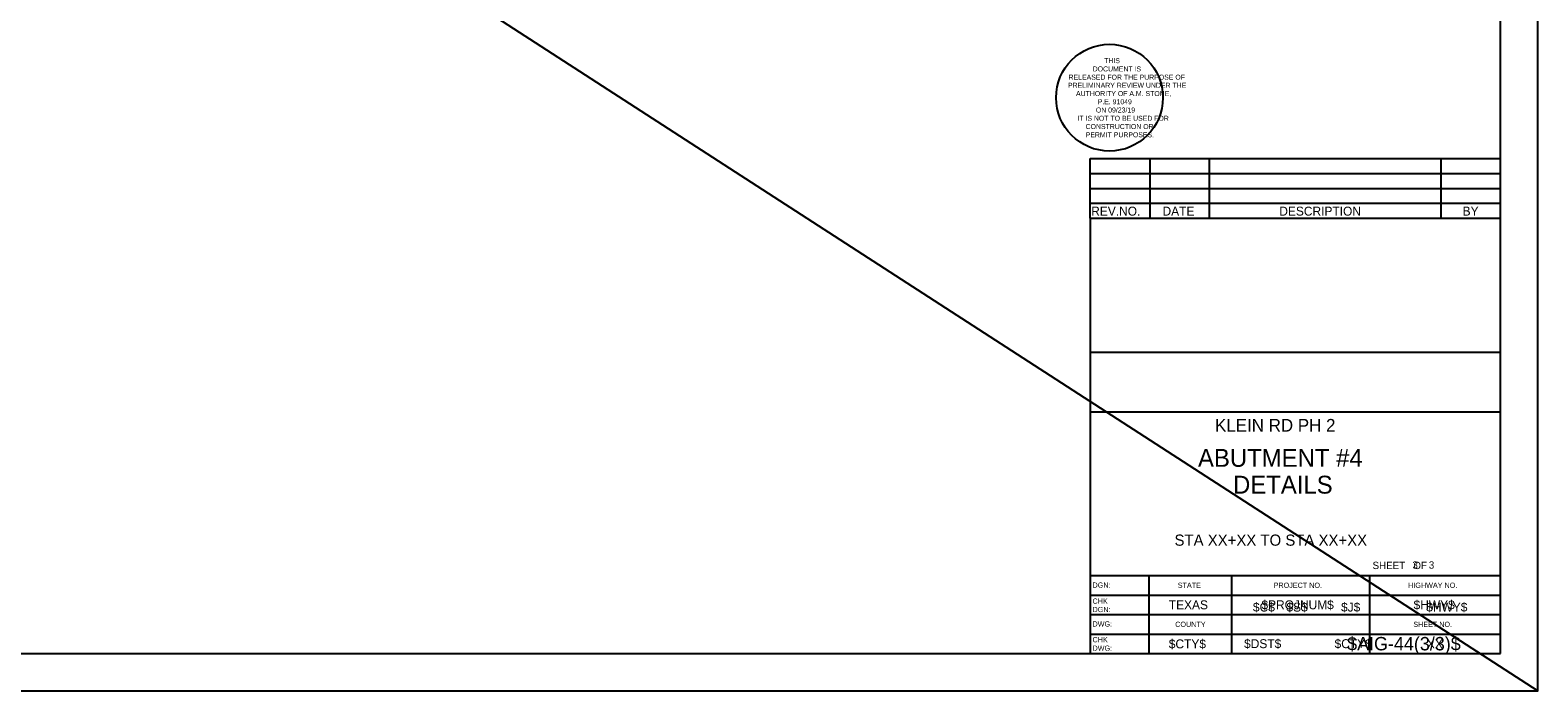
# Model space of a CAD drawing. Extents: x 926 to 1074, y 990 to 1081.
# Drawn here: x 1013.75 to 1034, y 1023 to 1031.88 of the extents above; entities that cross this region are included whole.
import ezdxf

# ---------------------------------------------------------------- set-up
doc = ezdxf.new("R2010")
doc.units = 0
for name, color, linetype in [('BORD_lines_major', 7, 'Continuous'), ('BORD_lines_minor', 7, 'Continuous'), ('BORD_text_large_1', 7, 'Continuous'), ('BORD_text_large_2', 7, 'Continuous'), ('BORD_text_SHEET', 7, 'Continuous'), ('BORD_text_small_1', 7, 'Continuous'), ('BORD_text_small_3', 7, 'Continuous'), ('BORD_text_small_proj', 7, 'Continuous'), ('C-MS-ANNO-TTLB-STMP', 7, 'Continuous'), ('D_BATCH_PLOT', 7, 'Continuous'), ('D_SHEET', 7, 'Continuous'), ('D_SHEET_NUM_CODE', 7, 'Continuous'), ('D_SHEET_TXT_SUB_CODE', 7, 'Continuous'), ('Working Level 1', 7, 'Continuous')]:
    doc.layers.add(name, color=color, linetype=linetype)

msp = doc.modelspace()

# ---------------------------------------------------------------- linework, layer by layer
at = {"layer": 'BORD_lines_major'}
for p, q in [((1033.5, 1023.5), (1033.5, 1044.382)), ((1002.413, 1023.5), (1033.5, 1023.5))]:
    msp.add_line(p, q, dxfattribs=at)
at = {"layer": 'BORD_lines_minor'}
for p, q in [((1027.988, 1030.15), (1033.5, 1030.15)), ((1027.988, 1029.35), (1027.988, 1030.15)), ((1028.788, 1030.15), (1028.788, 1029.35)), ((1029.588, 1030.15), (1029.588, 1029.35)), ((1032.7, 1029.35), (1032.7, 1030.15)), ((1027.988, 1029.95), (1033.5, 1029.95)), ((1027.988, 1029.75), (1033.5, 1029.75)), ((1027.988, 1029.55), (1033.5, 1029.55)), ((1027.988, 1029.35), (1033.5, 1029.35)), ((1027.988, 1029.35), (1027.988, 1027.55)), ((1027.988, 1027.55), (1033.5, 1027.55)), ((1027.988, 1027.55), (1027.988, 1023.5)), ((1027.988, 1026.75), (1033.5, 1026.75)), ((1027.988, 1024.55), (1033.5, 1024.55)), ((1028.776, 1024.55), (1028.776, 1023.5)), ((1029.888, 1024.55), (1029.888, 1023.5)), ((1031.738, 1024.55), (1031.738, 1023.5)), ((1027.988, 1024.287), (1033.5, 1024.287)), ((1027.988, 1024.025), (1033.5, 1024.025)), ((1027.988, 1023.762), (1033.5, 1023.762))]:
    msp.add_line(p, q, dxfattribs=at)
at = {"layer": 'C-MS-ANNO-TTLB-STMP'}
msp.add_circle((1028.248, 1030.969), 0.717, dxfattribs=at)
at = {"layer": 'D_BATCH_PLOT'}
msp.add_lwpolyline([(1000, 1023), (1034, 1023), (1034, 1045), (1000, 1045)], close=True, dxfattribs=at)
at = {"layer": 'D_SHEET'}
for p, q in [((1034, 1023), (1034, 1045)), ((1000, 1023), (1034, 1023))]:
    msp.add_line(p, q, dxfattribs=at)
at = {"layer": 'Working Level 1'}
msp.add_line((1000, 1045), (1034, 1023), dxfattribs=at)

# ---------------------------------------------------------------- texts
at = {"layer": 'BORD_lines_minor'}
for s, p in [('REV.NO.', (1028.002, 1029.385)), ('DATE', (1028.96, 1029.385)), ('DESCRIPTION', (1030.528, 1029.385)), ('BY', (1032.99, 1029.385))]:
    msp.add_text(s, height=0.12, rotation=359.9834, dxfattribs=at).set_placement(p)
msp.add_text('KLEIN RD PH 2', height=0.17, dxfattribs=at).set_placement((1029.665, 1026.483))
at = {"layer": 'BORD_text_large_1'}
for s, p in [('ABUTMENT #4', (1029.436, 1026.01)), ('DETAILS', (1029.907, 1025.65))]:
    msp.add_text(s, height=0.24, dxfattribs=at).set_placement(p)
at = {"layer": 'BORD_text_large_2'}
msp.add_text('STA XX+XX TO STA XX+XX', height=0.15, dxfattribs=at).set_placement((1029.121, 1024.95))
at = {"layer": 'BORD_text_SHEET'}
msp.add_text('XX', height=0.12, dxfattribs=at).set_placement((1032.51, 1023.571))
at = {"layer": 'BORD_text_small_1'}
msp.add_text('SHEET   OF', height=0.0984, dxfattribs=at).set_placement((1031.78, 1024.636))
at = {"layer": 'BORD_text_small_3'}
msp.add_text('3    3', height=0.0984, dxfattribs=at).set_placement((1032.316, 1024.642))
at = {"layer": 'BORD_text_small_proj'}
for s, height, p in [('DGN:', 0.07, (1028.02, 1024.386)), ('STATE', 0.07, (1029.164, 1024.384)), ('PROJECT NO.', 0.07, (1030.452, 1024.384)), ('HIGHWAY NO.', 0.07, (1032.258, 1024.384)), ('CHK', 0.07, (1028.02, 1024.171)), ('DGN:', 0.07, (1028.02, 1024.058)), ('TEXAS', 0.12, (1029.044, 1024.096)), ('$HWY$', 0.12, (1032.331, 1024.096)), ('DWG:', 0.07, (1028.02, 1023.864)), ('COUNTY', 0.07, (1029.13, 1023.859)), ('SHEET NO.', 0.07, (1032.327, 1023.859)), ('CHK', 0.07, (1028.02, 1023.653)), ('$CTY$', 0.12, (1029.044, 1023.571)), ('DWG:', 0.07, (1028.02, 1023.539))]:
    msp.add_text(s, height=height, rotation=359.9834, dxfattribs=at).set_placement(p)
msp.add_text('$PROJNUM$', height=0.12, dxfattribs=at).set_placement((1030.288, 1024.096))
at = {"layer": 'C-MS-ANNO-TTLB-STMP'}
for s, height, p in [('DOCUMENT IS', 0.06723, (1028.022, 1031.322)), ('THIS', 0.0672, (1028.176, 1031.433)), ('PRELIMINARY REVIEW UNDER THE', 0.06723, (1027.69, 1031.102)), ('RELEASED FOR THE PURPOSE OF', 0.06723, (1027.698, 1031.211)), ('AUTHORITY OF A.M. STONE,', 0.06723, (1027.798, 1030.991)), ('ON 09/23/19', 0.06723, (1028.065, 1030.77)), ('P.E. 91049', 0.0672, (1028.089, 1030.881)), ('IT IS NOT TO BE USED FOR', 0.06723, (1027.817, 1030.659)), ('CONSTRUCTION OR', 0.06723, (1027.927, 1030.548)), ('PERMIT PURPOSES.', 0.06723, (1027.928, 1030.437))]:
    msp.add_text(s, height=height, rotation=360, dxfattribs=at).set_placement(p)
at = {"layer": 'D_SHEET_NUM_CODE'}
msp.add_text('$AIG-44(3/3)$', height=0.18, dxfattribs=at).set_placement((1031.439, 1023.544))
at = {"layer": 'D_SHEET_TXT_SUB_CODE'}
for s, p in [('$C$', (1030.174, 1024.065)), ('$S$', (1030.624, 1024.065)), ('$J$', (1031.357, 1024.065)), ('$HWY$', (1032.501, 1024.065)), ('$DST$', (1030.055, 1023.574)), ('$CTY$', (1031.27, 1023.574))]:
    msp.add_text(s, height=0.12, dxfattribs=at).set_placement(p)

doc.saveas('drawing.dxf')
